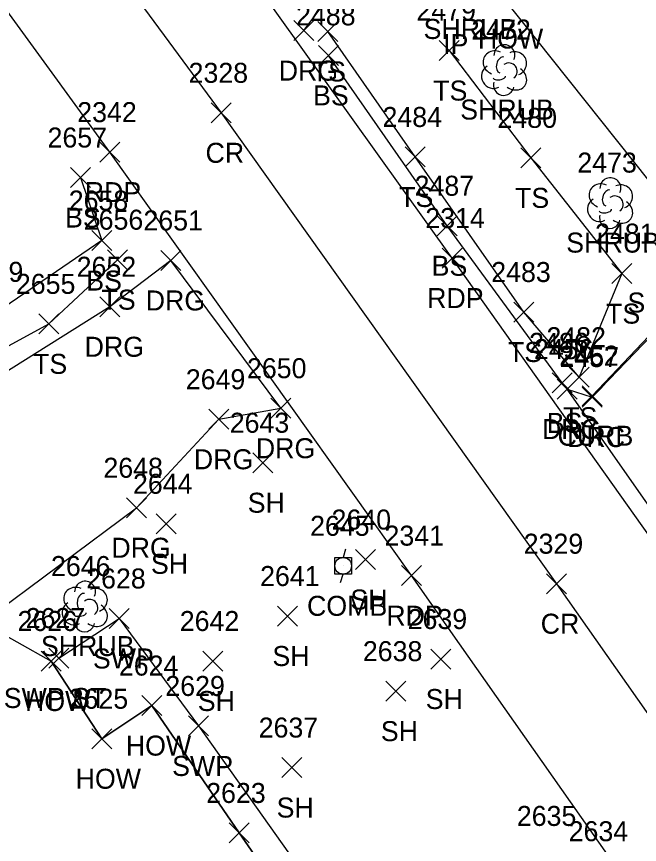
# Model space of a CAD drawing. Extents: x 1638344 to 1639591, y 610835 to 612202.
# Drawn here: x 1638944.8 to 1639007.1, y 611458.3 to 611541.1 of the extents above; entities that cross this region are included whole.
import ezdxf

# ---------------------------------------------------------------- set-up
doc = ezdxf.new("R2010")
doc.units = 0
for name, color, linetype in [('L_A', 7, 'Continuous'), ('L_I', 7, 'Continuous'), ('L_TIC', 7, 'Continuous'), ('LBC', 7, 'Continuous'), ('LELB', 7, 'Continuous'), ('LSH', 7, 'Continuous'), ('LSOGP', 7, 'Continuous'), ('M_A', 7, 'Continuous'), ('P_A', 7, 'Continuous'), ('P_I', 7, 'Continuous'), ('P_TIC', 7, 'Continuous'), ('PET', 7, 'Continuous'), ('PRC', 7, 'Continuous'), ('R_A', 7, 'Continuous'), ('R_I', 7, 'Continuous'), ('R_TIC', 7, 'Continuous'), ('RC', 7, 'Continuous'), ('RDG', 7, 'Continuous'), ('RDP', 7, 'Continuous'), ('RSW', 7, 'Continuous'), ('U_A', 7, 'Continuous'), ('U_I', 7, 'Continuous'), ('UP', 7, 'Continuous')]:
    doc.layers.add(name, color=color, linetype=linetype)

msp = doc.modelspace()

# ---------------------------------------------------------------- linework, layer by layer
at = {"layer": 'L_TIC'}
for points in [[(1638974.954, 611538.561), (1638976.954, 611540.561)], [(1638976.954, 611538.561), (1638974.954, 611540.561)], [(1638987.097, 611536.652), (1638989.097, 611538.652)], [(1638989.097, 611536.652), (1638987.097, 611538.652)], [(1638975.053, 611536.173), (1638977.053, 611538.173)], [(1638977.053, 611536.173), (1638975.053, 611538.173)], [(1638983.698, 611526.012), (1638985.698, 611528.012)], [(1638985.698, 611526.012), (1638983.698, 611528.012)], [(1638995.279, 611525.923), (1638997.279, 611527.923)], [(1638997.279, 611525.923), (1638995.279, 611527.923)], [(1638950.253, 611523.958), (1638952.253, 611525.958)], [(1638952.253, 611523.958), (1638950.253, 611525.958)], [(1638986.906, 611519.135), (1638988.906, 611521.135)], [(1638988.906, 611519.135), (1638986.906, 611521.135)], [(1638952.372, 611517.656), (1638954.372, 611519.656)], [(1638954.372, 611517.656), (1638952.372, 611519.656)], [(1638953.928, 611515.743), (1638955.928, 611517.743)], [(1638955.928, 611515.743), (1638953.928, 611517.743)], [(1639004.38, 611514.348), (1639006.38, 611516.348)], [(1639006.38, 611514.348), (1639004.38, 611516.348)], [(1638994.57, 611510.51), (1638996.57, 611512.51)], [(1638996.57, 611510.51), (1638994.57, 611512.51)], [(1638947.087, 611509.326), (1638949.087, 611511.326)], [(1638949.087, 611509.326), (1638947.087, 611511.326)], [(1638998.409, 611503.423), (1639000.409, 611505.423)], [(1639000.409, 611503.423), (1638998.409, 611505.423)], [(1639000.089, 611503.988), (1639002.089, 611505.988)], [(1639002.089, 611503.988), (1639000.089, 611505.988)], [(1638968.468, 611495.438), (1638970.468, 611497.438)], [(1638970.468, 611495.438), (1638968.468, 611497.438)], [(1638958.796, 611489.329), (1638960.796, 611491.329)], [(1638960.796, 611489.329), (1638958.796, 611491.329)], [(1638978.737, 611485.756), (1638980.737, 611487.756)], [(1638980.737, 611485.756), (1638978.737, 611487.756)], [(1638970.939, 611480.11), (1638972.939, 611482.11)], [(1638972.939, 611480.11), (1638970.939, 611482.11)], [(1638947.307, 611475.612), (1638949.307, 611477.612)], [(1638949.307, 611475.612), (1638947.307, 611477.612)], [(1638963.475, 611475.612), (1638965.475, 611477.612)], [(1638965.475, 611475.612), (1638963.475, 611477.612)], [(1638986.267, 611475.809), (1638988.267, 611477.809)], [(1638988.267, 611475.809), (1638986.267, 611477.809)], [(1638981.779, 611472.597), (1638983.779, 611474.597)], [(1638983.779, 611472.597), (1638981.779, 611474.597)], [(1638957.386, 611471.153), (1638959.386, 611473.153)], [(1638959.386, 611471.153), (1638957.386, 611473.153)], [(1638952.366, 611467.836), (1638954.366, 611469.836)], [(1638954.366, 611467.836), (1638952.366, 611469.836)], [(1638971.362, 611464.956), (1638973.362, 611466.956)], [(1638973.362, 611464.956), (1638971.362, 611466.956)], [(1638966.116, 611458.417), (1638968.116, 611460.417)], [(1638968.116, 611458.417), (1638966.116, 611460.417)]]:
    msp.add_lwpolyline(points, dxfattribs=at)
at = {"layer": 'LBC'}
for points in [[(1639026.748, 611528.452), (1639021.663, 611524.358), (1639015.341, 611519.249), (1639013.241, 611521.802), (1639011.378, 611520.532), (1638993.589, 611542.858), (1639005.17, 611552.615)], [(1638967.493, 611433.085), (1638975.17, 611438.042), (1638970.751, 611444.755), (1638975.069, 611447.924), (1638967.116, 611459.417), (1638958.386, 611472.153), (1638953.366, 611468.836), (1638948.307, 611476.612)]]:
    msp.add_lwpolyline(points, dxfattribs=at)
at = {"layer": 'LELB'}
for points in [[(1638988.097, 611537.652), (1638996.279, 611526.923), (1639005.38, 611515.348), (1639001.089, 611504.988), (1638995.57, 611511.51), (1638984.698, 611527.012), (1638975.954, 611539.561)], [(1638999.409, 611504.423), (1638987.906, 611520.135), (1638976.053, 611537.173)], [(1638951.253, 611524.958), (1638953.372, 611518.656), (1638942.893, 611511.526), (1638930.918, 611504.473)], [(1638933.494, 611502.399), (1638948.087, 611510.326), (1638954.928, 611516.743)]]:
    msp.add_lwpolyline(points, dxfattribs=at)
at = {"layer": 'LSH'}
for p, q in [((1638993.576, 611535.755), (1638993.576, 611535.755)), ((1638993.576, 611535.755), (1638993.576, 611535.755)), ((1639004.176, 611522.451), (1639004.176, 611522.451)), ((1639004.176, 611522.451), (1639004.176, 611522.451)), ((1638951.653, 611482.107), (1638951.653, 611482.107)), ((1638951.653, 611482.107), (1638951.653, 611482.107))]:
    msp.add_line(p, q, dxfattribs=at)
for centre in [(1638993.623, 611537.189), (1639004.223, 611523.885), (1638951.7, 611483.541)]:
    msp.add_arc(centre, 1.047, 335.52715, 180.95627, dxfattribs=at)
for centre, major_axis, ratio, start_param, end_param in [((1638992.784, 611536.422), (1.21, -0.512), 0.895232, 1.570796, 4.712389), ((1638994.618, 611536.339), (-1.141, -0.483), 0.949671, 1.570796, 4.712389), ((1638993.368, 611536.213), (-0.208, -0.792), 0.645439, 3.141593, 6.283185), ((1638992.493, 611535.046), (0.584, -1.042), 0.959034, 3.141593, 6.283185), ((1638994.076, 611535.588), (-0.5, 0.667), 0.989748, 3.141593, 6.283185), ((1638994.576, 611534.922), (-1.09, 0.792), 0.841452, 1.570796, 4.712389), ((1638993.576, 611534.255), (0.265, 1.061), 0.942809, 1.570796, 4.712389), ((1638993.118, 611535.005), (-0.625, -0.083), 0.423636, 0, 3.141593), ((1639003.384, 611523.118), (1.21, -0.512), 0.895232, 1.570796, 4.712389), ((1639003.968, 611522.909), (-0.208, -0.792), 0.645439, 3.141593, 6.283185), ((1639005.218, 611523.035), (-1.141, -0.483), 0.949671, 1.570796, 4.712389), ((1639004.676, 611522.284), (-0.5, 0.667), 0.989748, 3.141593, 6.283185), ((1639003.093, 611521.742), (0.584, -1.042), 0.959034, 3.141593, 6.283185), ((1639005.176, 611521.618), (-1.09, 0.792), 0.841452, 1.570796, 4.712389), ((1639004.176, 611520.951), (0.265, 1.061), 0.942809, 1.570796, 4.712389), ((1639003.718, 611521.701), (-0.625, -0.083), 0.423636, 0, 3.141593), ((1638950.861, 611482.774), (1.21, -0.512), 0.895232, 1.570796, 4.712389), ((1638952.695, 611482.691), (-1.141, -0.483), 0.949671, 1.570796, 4.712389), ((1638951.445, 611482.565), (-0.208, -0.792), 0.645439, 3.141593, 6.283185), ((1638950.57, 611481.398), (0.584, -1.042), 0.959034, 3.141593, 6.283185), ((1638952.153, 611481.94), (-0.5, 0.667), 0.989748, 3.141593, 6.283185), ((1638951.195, 611481.357), (-0.625, -0.083), 0.423636, 0, 3.141593), ((1638952.653, 611481.274), (-1.09, 0.792), 0.841452, 1.570796, 4.712389), ((1638951.653, 611480.607), (0.265, 1.061), 0.942809, 1.570796, 4.712389)]:
    msp.add_ellipse(centre, major_axis=major_axis, ratio=ratio, start_param=start_param, end_param=end_param, dxfattribs=at)
at = {"layer": 'LSOGP'}
msp.add_lwpolyline([(1638866.348, 611571.464), (1638891.21, 611537.156), (1638898.264, 611527.189), (1638908.025, 611525.06), (1638919.127, 611516.129), (1638930.918, 611504.473), (1638933.494, 611502.399), (1638935.836, 611500.513), (1638941.41, 611480.463), (1638948.307, 611476.612), (1638953.366, 611468.836), (1638958.386, 611472.153), (1638967.116, 611459.417), (1638975.069, 611447.924), (1638970.751, 611444.755), (1638975.17, 611438.042), (1638967.493, 611433.085), (1638975.646, 611412.074), (1638983.021, 611400.9), (1638992.437, 611393.679), (1638995.764, 611397.426), (1639012.693, 611385.24), (1639028.133, 611374.158)], dxfattribs=at)
at = {"layer": 'P_TIC'}
for points in [[(1638964.308, 611530.428), (1638966.308, 611532.428)], [(1638966.308, 611530.428), (1638964.308, 611532.428)], [(1638953.173, 611526.497), (1638955.173, 611528.497)], [(1638955.173, 611526.497), (1638953.173, 611528.497)], [(1638987.412, 611515.904), (1638989.412, 611517.904)], [(1638989.412, 611515.904), (1638987.412, 611517.904)], [(1638983.33, 611484.148), (1638985.33, 611486.148)], [(1638985.33, 611484.148), (1638983.33, 611486.148)], [(1638997.822, 611483.341), (1638999.822, 611485.341)], [(1638999.822, 611483.341), (1638997.822, 611485.341)]]:
    msp.add_lwpolyline(points, dxfattribs=at)
at = {"layer": 'PET'}
for points in [[(1639148.644, 611331.084), (1639142.07, 611329.181), (1639135.695, 611328.741), (1639125.685, 611331.146), (1639119.176, 611334.876), (1639114.186, 611340.569), (1639098.763, 611361.782), (1639080.318, 611387.337), (1639061.62, 611413.479), (1639039.15, 611444.22), (1639014.337, 611480.362), (1638988.412, 611516.904), (1638963.389, 611551.848), (1638935.462, 611588.701), (1638918.51, 611609.364), (1638899.727, 611630.857), (1638874.406, 611653.859), (1638846.552, 611674.469), (1638833.143, 611682.537), (1638823.865, 611689.161)], [(1639117.365, 611283.377), (1639114.123, 611301.894), (1639095.515, 611328.502), (1639070.515, 611363.262), (1639041.381, 611404.693), (1639011.578, 611446.402), (1638984.33, 611485.148), (1638954.173, 611527.497), (1638934.327, 611554.774), (1638918.881, 611575.585), (1638893.271, 611605.667), (1638868.117, 611629.836), (1638836.66, 611652.855), (1638812.431, 611667.635)]]:
    msp.add_lwpolyline(points, dxfattribs=at)
at = {"layer": 'PRC'}
msp.add_lwpolyline([(1638818.793, 611678.836), (1638843.976, 611663.347), (1638876.437, 611637.386), (1638906.243, 611607.195), (1638934.14, 611573.691), (1638965.308, 611531.428), (1638998.822, 611484.341), (1639033.825, 611434.483), (1639068.011, 611386.3), (1639093.943, 611350.49), (1639111.892, 611325.375), (1639129.228, 611302.77)], dxfattribs=at)
at = {"layer": 'R_TIC'}
for points in [[(1638972.572, 611538.646), (1638974.572, 611540.646)], [(1638974.572, 611538.646), (1638972.572, 611540.646)], [(1638959.272, 611515.664), (1638961.272, 611517.664)], [(1638961.272, 611515.664), (1638959.272, 611517.664)], [(1638953.163, 611511.035), (1638955.163, 611513.035)], [(1638955.163, 611511.035), (1638953.163, 611513.035)], [(1638998.895, 611502.8), (1639000.895, 611504.8)], [(1639000.895, 611502.8), (1638998.895, 611504.8)], [(1639001.398, 611502.006), (1639003.398, 611504.006)], [(1639003.398, 611502.006), (1639001.398, 611504.006)], [(1639001.408, 611502.14), (1639003.408, 611504.14)], [(1639003.408, 611502.14), (1639001.408, 611504.14)], [(1638970.282, 611500.89), (1638972.282, 611502.89)], [(1638972.282, 611500.89), (1638970.282, 611502.89)], [(1638964.085, 611499.785), (1638966.085, 611501.785)], [(1638966.085, 611499.785), (1638964.085, 611501.785)], [(1638955.837, 611490.936), (1638957.837, 611492.936)], [(1638957.837, 611490.936), (1638955.837, 611492.936)], [(1638954.118, 611479.864), (1638956.118, 611481.864)], [(1638956.118, 611479.864), (1638954.118, 611481.864)], [(1638948.068, 611475.91), (1638950.068, 611477.91)], [(1638950.068, 611475.91), (1638948.068, 611477.91)], [(1638962.038, 611469.116), (1638964.038, 611471.116)], [(1638964.038, 611469.116), (1638962.038, 611471.116)]]:
    msp.add_lwpolyline(points, dxfattribs=at)
at = {"layer": 'RC'}
msp.add_lwpolyline([(1639015.446, 611519.023), (1639014.918, 611516.323), (1639002.408, 611503.14)], dxfattribs=at)
at = {"layer": 'RDG'}
for points in [[(1638973.572, 611539.646), (1638980.098, 611548.383), (1638989.33, 611555.306), (1638996.214, 611558.885), (1638997.591, 611567.179), (1638982.401, 611560.247), (1638966.545, 611551.684), (1638963.842, 611552.74)], [(1638941.41, 611480.463), (1638956.837, 611491.936), (1638965.085, 611500.785), (1638971.282, 611501.89), (1638960.272, 611516.664), (1638954.163, 611512.035), (1638935.836, 611500.513)]]:
    msp.add_lwpolyline(points, dxfattribs=at)
at = {"layer": 'RDP'}
msp.add_lwpolyline([(1639043.011, 611511.789), (1639032.473, 611500.709), (1639015.977, 611483.459), (1639015.731, 611481.189), (1638999.895, 611503.8), (1639002.398, 611503.006), (1639015.137, 611516.241), (1639015.6, 611519.115)], dxfattribs=at)
at = {"layer": 'RSW'}
msp.add_lwpolyline([(1638949.068, 611476.91), (1638955.118, 611480.864), (1638963.038, 611470.116), (1638981.063, 611444.712), (1638982.759, 611444.013)], dxfattribs=at)
at = {"layer": 'UP'}
for p, q in [((1638977.753, 611487.796), (1638977.503, 611486.962)), ((1638976.67, 611485.296), (1638976.67, 611486.962)), ((1638976.67, 611486.962), (1638978.336, 611486.962)), ((1638978.336, 611486.962), (1638978.336, 611485.296)), ((1638977.503, 611486.129), (1638977.503, 611486.129)), ((1638978.336, 611485.296), (1638976.67, 611485.296)), ((1638977.253, 611484.462), (1638977.503, 611485.296))]:
    msp.add_line(p, q, dxfattribs=at)
msp.add_circle((1638977.503, 611486.129), 0.833, dxfattribs=at)

# ---------------------------------------------------------------- texts
at = {"layer": 'L_A'}
for s, p in [('SHRUB', (1638985.544, 611538.813)), ('HOW', (1638990.975, 611537.858)), ('TS', (1638974.363, 611534.561)), ('TS', (1638986.506, 611532.652)), ('BS', (1638974.494, 611532.173)), ('SHRUB', (1638989.206, 611530.755)), ('TS', (1638983.107, 611522.012)), ('TS', (1638994.688, 611521.923)), ('BS', (1638949.694, 611519.958)), ('SHRUB', (1638999.806, 611517.451)), ('BS', (1638986.347, 611515.135)), ('BS', (1638951.813, 611513.656)), ('TS', (1638953.337, 611511.743)), ('SHRUB', (1639005.925, 611511.457)), ('TS', (1639003.789, 611510.348)), ('TS', (1638993.979, 611506.51)), ('TS', (1638946.496, 611505.326)), ('BS', (1638997.85, 611499.423)), ('TS', (1638999.498, 611499.988)), ('SH', (1638967.956, 611491.438)), ('SH', (1638958.284, 611485.329)), ('SH', (1638978.225, 611481.756)), ('SHRUB', (1638947.283, 611477.107)), ('SH', (1638970.427, 611476.11)), ('HOW', (1638945.693, 611471.612)), ('SH', (1638962.963, 611471.612)), ('SH', (1638985.755, 611471.809)), ('SH', (1638981.267, 611468.597)), ('HOW', (1638955.772, 611467.153)), ('HOW', (1638950.752, 611463.836)), ('SH', (1638970.85, 611460.956))]:
    msp.add_text(s, height=2, dxfattribs=at).set_placement(p)
at = {"layer": 'L_I'}
for s, p in [('2479', (1638984.829, 611540.652)), ('2488', (1638972.793, 611540.173)), ('2472', (1638990.316, 611538.755)), ('2484', (1638981.438, 611530.012)), ('2480', (1638992.933, 611529.923)), ('2657', (1638947.946, 611527.958)), ('2473', (1639000.916, 611525.451)), ('2487', (1638984.646, 611523.135)), ('2658', (1638950.065, 611521.656)), ('2656', (1638951.566, 611519.743)), ('2481', (1639002.687, 611518.348)), ('2659', (1638939.578, 611514.526)), ('2483', (1638992.31, 611514.51)), ('2655', (1638944.78, 611513.326)), ('2482', (1638997.829, 611507.988)), ('2486', (1638996.094, 611507.423)), ('2643', (1638966.161, 611499.438)), ('2644', (1638956.489, 611493.329)), ('2640', (1638976.343, 611489.756)), ('2646', (1638948.291, 611485.107)), ('2641', (1638969.199, 611484.11)), ('2626', (1638944.945, 611479.612)), ('2642', (1638961.168, 611479.612)), ('2639', (1638983.952, 611479.809)), ('2638', (1638979.472, 611476.597)), ('2624', (1638955.079, 611475.153)), ('2625', (1638950.059, 611471.836)), ('2637', (1638969.055, 611468.956)), ('2623', (1638963.809, 611462.417)), ('2635', (1638994.868, 611460.12))]:
    msp.add_text(s, height=2, dxfattribs=at).set_placement(p)
at = {"layer": 'M_A'}
msp.add_text('IP', height=2, dxfattribs=at).set_placement((1638987.495, 611537.294))
at = {"layer": 'P_A'}
for s, p in [('CR', (1638963.741, 611526.428)), ('RDP', (1638951.661, 611522.497)), ('RDP', (1638985.9, 611511.904)), ('RDP', (1638981.818, 611480.148)), ('CR', (1638997.255, 611479.341))]:
    msp.add_text(s, height=2, dxfattribs=at).set_placement(p)
at = {"layer": 'P_I'}
for s, p in [('2328', (1638962.048, 611534.428)), ('2342', (1638950.913, 611530.497)), ('2314', (1638985.719, 611519.904)), ('2341', (1638981.637, 611488.148)), ('2329', (1638995.554, 611487.341))]:
    msp.add_text(s, height=2, dxfattribs=at).set_placement(p)
at = {"layer": 'R_A'}
for s, p in [('DRG', (1638971.06, 611534.646)), ('DRG', (1638957.76, 611511.664)), ('DRG', (1638951.651, 611507.035)), ('DRC', (1638997.383, 611498.8)), ('CURB', (1638998.936, 611498.14)), ('DRC', (1638999.886, 611498.006)), ('DRG', (1638968.77, 611496.89)), ('DRG', (1638962.573, 611495.785)), ('DRG', (1638954.325, 611486.936)), ('SWP', (1638952.48, 611475.864)), ('SWP ST', (1638943.564, 611471.91)), ('SWP', (1638960.4, 611465.116))]:
    msp.add_text(s, height=2, dxfattribs=at).set_placement(p)
at = {"layer": 'R_I'}
for s, p in [('2651', (1638957.532, 611519.664)), ('2652', (1638950.856, 611515.035)), ('2456', (1638996.58, 611506.8)), ('2462', (1638999.101, 611506.14)), ('2457', (1638999.138, 611506.006)), ('2650', (1638967.888, 611504.89)), ('2649', (1638961.77, 611503.785)), ('2648', (1638953.53, 611494.936)), ('2628', (1638951.811, 611483.864)), ('2627', (1638945.761, 611479.91)), ('2629', (1638959.723, 611473.116)), ('2634', (1639000.049, 611458.591))]:
    msp.add_text(s, height=2, dxfattribs=at).set_placement(p)
at = {"layer": 'U_A'}
msp.add_text('COMB', height=2, dxfattribs=at).set_placement((1638973.889, 611481.129))
at = {"layer": 'U_I'}
msp.add_text('2645', height=2, dxfattribs=at).set_placement((1638974.196, 611489.129))

doc.saveas('drawing.dxf')
